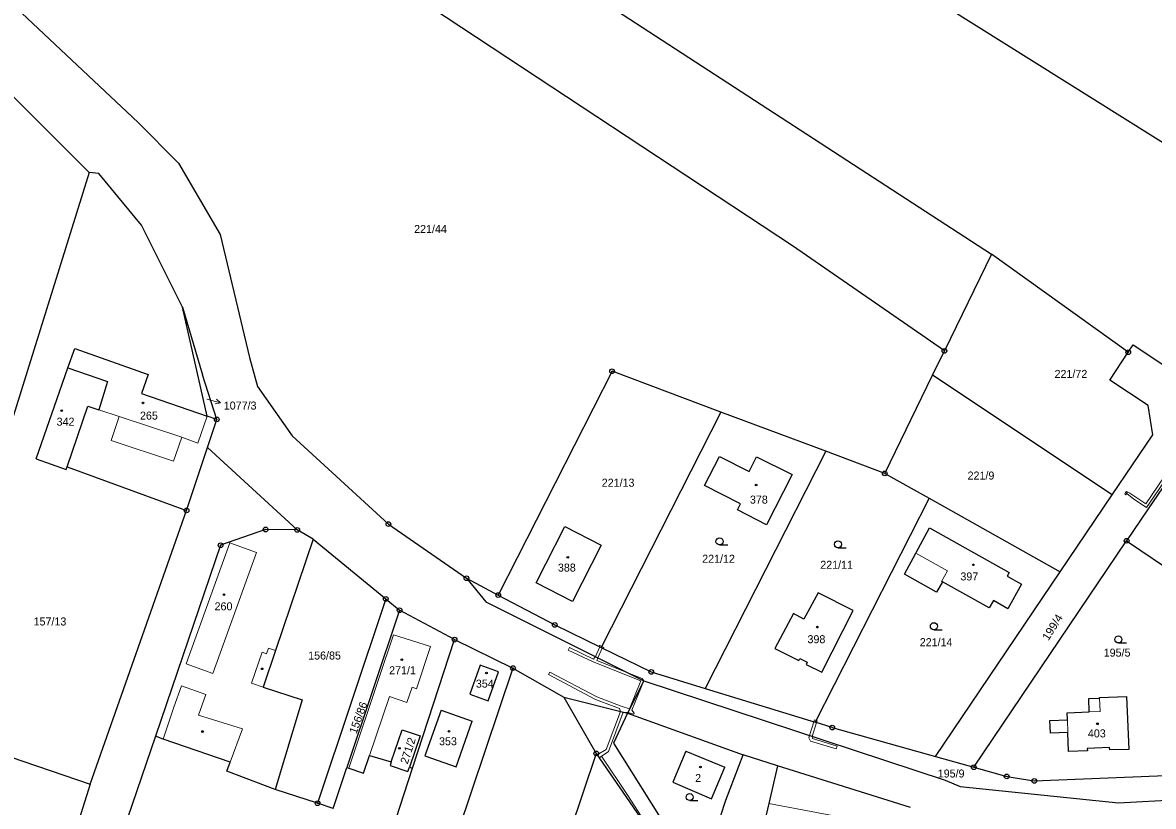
# Model space of a CAD drawing. Extents: x -694609 to -690140, y -1033292 to -1029794.
# Drawn here: x -693359.6 to -693119.3, y -1031245.2 to -1031078.6 of the extents above; entities that cross this region are included whole.
import ezdxf
from ezdxf.enums import TextEntityAlignment as Align

# ---------------------------------------------------------------- set-up
doc = ezdxf.new("R2010")
doc.units = 0
doc.header["$LTSCALE"] = 0.68
for name, color, linetype, lineweight in [('1', 7, 'Continuous', 25), ('13', 7, 'Continuous', 13), ('3', 7, 'Continuous', 25), ('4', 7, 'Continuous', 13), ('5', 7, 'Continuous', 25), ('7', 7, 'Continuous', 13), ('8', 7, 'Continuous', 25)]:
    doc.layers.add(name, color=color, linetype=linetype, lineweight=lineweight)
doc.layers.add('2', color=7, linetype='Continuous')

msp = doc.modelspace()

# ---------------------------------------------------------------- linework, layer by layer
at = {"layer": '1'}
for p, q in [((-693273.03, -1031050.26), (-693153.72, -1031127.85)), ((-693366.29, -1031070.45), (-693335.04, -1031099.87)), ((-693195.97, -1031126.12), (-693272.71, -1031075.54)), ((-693345.4, -1031110.52), (-693378.71, -1031077.22)), ((-693335.04, -1031099.87), (-693326.47, -1031108.49)), ((-693326.47, -1031108.49), (-693317.59, -1031123.7)), ((-693345.4, -1031110.52), (-693382.08, -1031227.92)), ((-693343.35, -1031110.73), (-693345.4, -1031110.52)), ((-693334.33, -1031121.69), (-693343.35, -1031110.73)), ((-693325.6, -1031139.11), (-693334.33, -1031121.69)), ((-693317.59, -1031123.7), (-693311.38, -1031149.83)), ((-693163.72, -1031148.41), (-693195.97, -1031126.12)), ((-693153.72, -1031127.85), (-693163.72, -1031148.41)), ((-693124.65, -1031148.71), (-693153.72, -1031127.85)), ((-693320.34, -1031162.28), (-693325.6, -1031139.11)), ((-693325.6, -1031139.11), (-693321.37, -1031153.47)), ((-693349.93, -1031152.01), (-693348.5, -1031147.93)), ((-693348.5, -1031147.93), (-693332.89, -1031153.42)), ((-693124.65, -1031148.71), (-693123.6, -1031147.13)), ((-693123.6, -1031147.13), (-693109.83, -1031156.28)), ((-693311.38, -1031149.83), (-693309.64, -1031155.96)), ((-693166.24, -1031153.6), (-693163.72, -1031148.41)), ((-693128.58, -1031154.62), (-693124.65, -1031148.71)), ((-693356.71, -1031171.36), (-693349.93, -1031152.01)), ((-693349.93, -1031152.01), (-693341.56, -1031154.91)), ((-693234.33, -1031152.75), (-693258.53, -1031200.3)), ((-693211.19, -1031161.42), (-693234.33, -1031152.75)), ((-693341.56, -1031154.91), (-693343.41, -1031160.93)), ((-693332.89, -1031153.42), (-693334.28, -1031157.44)), ((-693318.31, -1031162.97), (-693321.37, -1031153.47)), ((-693176.39, -1031174.45), (-693166.24, -1031153.6)), ((-693128.05, -1031178.99), (-693166.24, -1031153.6)), ((-693120.44, -1031160.04), (-693128.58, -1031154.62)), ((-693334.28, -1031157.44), (-693320.34, -1031162.28)), ((-693309.64, -1031155.96), (-693302.31, -1031166.48)), ((-693119.46, -1031166.26), (-693120.44, -1031160.04)), ((-693350.1, -1031173.03), (-693345.74, -1031160.15)), ((-693345.74, -1031160.15), (-693343.41, -1031160.93)), ((-693318.31, -1031162.97), (-693320.34, -1031162.28)), ((-693211.19, -1031161.42), (-693236.66, -1031211.46)), ((-693188.93, -1031169.75), (-693211.19, -1031161.42)), ((-693320.29, -1031168.95), (-693318.31, -1031162.97)), ((-693302.31, -1031166.48), (-693281.85, -1031185.23)), ((-693128.05, -1031178.99), (-693119.46, -1031166.26)), ((-693324.73, -1031182.33), (-693320.29, -1031168.95)), ((-693301.23, -1031186.45), (-693320.29, -1031168.95)), ((-693356.71, -1031171.36), (-693350.33, -1031173.61)), ((-693214.66, -1031177.03), (-693211.49, -1031170.86)), ((-693188.93, -1031169.75), (-693214.58, -1031220.15)), ((-693203.63, -1031170.91), (-693196.07, -1031174.71)), ((-693176.39, -1031174.45), (-693188.93, -1031169.75)), ((-693112.4, -1031170.1), (-693120.58, -1031182.22)), ((-693350.33, -1031173.61), (-693350.1, -1031173.03)), ((-693350.1, -1031173.03), (-693324.73, -1031182.33)), ((-693176.39, -1031174.45), (-693166.97, -1031179.73)), ((-693196.07, -1031174.71), (-693201.5, -1031185.39)), ((-693207.05, -1031180.94), (-693214.66, -1031177.03)), ((-693139.1, -1031195.36), (-693128.05, -1031178.99)), ((-693207.7, -1031182.21), (-693207.05, -1031180.94)), ((-693166.97, -1031179.73), (-693191.19, -1031227.33)), ((-693166.97, -1031179.73), (-693139.1, -1031195.36)), ((-693345.22, -1031240.5), (-693324.73, -1031182.33)), ((-693201.5, -1031185.39), (-693207.7, -1031182.21)), ((-693120.58, -1031182.22), (-693125, -1031188.77)), ((-693307.93, -1031186.37), (-693317.51, -1031189.73)), ((-693301.23, -1031186.45), (-693307.93, -1031186.37)), ((-693297.86, -1031188.42), (-693301.23, -1031186.45)), ((-693281.85, -1031185.23), (-693265.27, -1031196.73)), ((-693169.78, -1031191.37), (-693166.86, -1031186.01)), ((-693297.86, -1031188.42), (-693305.83, -1031212.11)), ((-693297.86, -1031188.42), (-693282.42, -1031201.11)), ((-693157.47, -1031236.89), (-693125, -1031188.77)), ((-693125, -1031188.77), (-693105.98, -1031201.7)), ((-693317.51, -1031189.73), (-693331.34, -1031230.32)), ((-693165.59, -1031234.62), (-693139.1, -1031195.36)), ((-693265.27, -1031196.73), (-693258.53, -1031200.3)), ((-693265.27, -1031196.73), (-693261.13, -1031201.72)), ((-693258.53, -1031200.3), (-693246.51, -1031206.66)), ((-693190.56, -1031199.84), (-693193.56, -1031205.43)), ((-693183.14, -1031203.56), (-693190.56, -1031199.84)), ((-693282.42, -1031201.11), (-693296.9, -1031244.56)), ((-693282.42, -1031201.11), (-693279.48, -1031203.53)), ((-693279.48, -1031203.53), (-693290.7, -1031236.94)), ((-693267.8, -1031209.78), (-693279.48, -1031203.53)), ((-693195.79, -1031204.25), (-693199.73, -1031211.69)), ((-693193.56, -1031205.43), (-693195.79, -1031204.25)), ((-693189.77, -1031216.72), (-693183.14, -1031203.56)), ((-693246.51, -1031206.66), (-693236.66, -1031211.46)), ((-693276.73, -1031237.11), (-693267.8, -1031209.78)), ((-693267.8, -1031209.78), (-693255.38, -1031215.82)), ((-693199.73, -1031211.69), (-693194.67, -1031214.24)), ((-693262.36, -1031215.21), (-693264.52, -1031221.39)), ((-693258.49, -1031216.6), (-693262.36, -1031215.21)), ((-693194.67, -1031214.24), (-693194.46, -1031213.76)), ((-693194.46, -1031213.76), (-693192.89, -1031214.58)), ((-693192.89, -1031214.58), (-693193.1, -1031215.06)), ((-693193.1, -1031215.06), (-693189.77, -1031216.72)), ((-693255.38, -1031215.82), (-693331.24, -1031440.29)), ((-693260.66, -1031222.76), (-693258.49, -1031216.6)), ((-693255.38, -1031215.82), (-693244.56, -1031222)), ((-693227.57, -1031218.56), (-693163.55, -1031239.63)), ((-693264.52, -1031221.39), (-693260.66, -1031222.76)), ((-693244.56, -1031222), (-693237.69, -1031233.95)), ((-693244.56, -1031222), (-693231.03, -1031225.43)), ((-693214.58, -1031220.15), (-693191.19, -1031227.33)), ((-693133.07, -1031222.3), (-693130.74, -1031222.24)), ((-693132.96, -1031225.13), (-693133.07, -1031222.3)), ((-693130.75, -1031222.07), (-693125.02, -1031221.85)), ((-693130.74, -1031222.24), (-693130.75, -1031222.07)), ((-693125.02, -1031221.85), (-693124.57, -1031233.09)), ((-693300.14, -1031222.56), (-693305.89, -1031241.6)), ((-693270.67, -1031224.73), (-693274.14, -1031234.44)), ((-693270.67, -1031224.73), (-693264.03, -1031227.09)), ((-693267.48, -1031236.81), (-693264.03, -1031227.09)), ((-693231.03, -1031225.43), (-693234.03, -1031231.76)), ((-693231.03, -1031225.43), (-693206.5, -1031234.28)), ((-693187.54, -1031228.45), (-693191.19, -1031227.33)), ((-693141.29, -1031226.95), (-693137.59, -1031226.83)), ((-693141.19, -1031229.62), (-693141.29, -1031226.95)), ((-693137.64, -1031225.3), (-693132.96, -1031225.13)), ((-693137.59, -1031226.83), (-693137.64, -1031225.3)), ((-693382.08, -1031227.92), (-693345.22, -1031240.5)), ((-693281.24, -1031235.78), (-693278.94, -1031228.94)), ((-693278.94, -1031228.94), (-693275.07, -1031230.25)), ((-693187.54, -1031228.45), (-693165.59, -1031234.62)), ((-693137.5, -1031229.5), (-693141.19, -1031229.62)), ((-693137.37, -1031233.54), (-693137.5, -1031229.5)), ((-693331.34, -1031230.32), (-693349.69, -1031284.17)), ((-693329.74, -1031230.95), (-693331.34, -1031230.32)), ((-693315.48, -1031235.85), (-693329.74, -1031230.95)), ((-693275.07, -1031230.25), (-693277.4, -1031236.91)), ((-693234.03, -1031231.76), (-693215.77, -1031260.84)), ((-693237.69, -1031233.95), (-693309.85, -1031446.55)), ((-693287.14, -1031238.13), (-693285.88, -1031234.42)), ((-693285.88, -1031234.42), (-693281.24, -1031235.78)), ((-693274.14, -1031234.44), (-693267.48, -1031236.81)), ((-693218.67, -1031233.45), (-693221.45, -1031240.1)), ((-693218.67, -1031233.45), (-693210.34, -1031236.89)), ((-693210.16, -1031243.87), (-693206.5, -1031234.28)), ((-693199.19, -1031236.57), (-693206.5, -1031234.28)), ((-693133.34, -1031233.4), (-693137.37, -1031233.54)), ((-693128.59, -1031233.16), (-693128.61, -1031232.73)), ((-693124.57, -1031233.09), (-693128.59, -1031233.16)), ((-693316.18, -1031237.7), (-693315.48, -1031235.85)), ((-693293.58, -1031245.65), (-693290.7, -1031236.94)), ((-693290.7, -1031236.94), (-693290.24, -1031237.12)), ((-693281.24, -1031235.78), (-693281.48, -1031236.51)), ((-693281.48, -1031236.51), (-693277.71, -1031237.8)), ((-693277.71, -1031237.8), (-693277.4, -1031236.91)), ((-693277.4, -1031236.91), (-693276.73, -1031237.11)), ((-693213.23, -1031243.61), (-693210.34, -1031236.89)), ((-693199.19, -1031236.57), (-693201.04, -1031244.57)), ((-693170.92, -1031245.42), (-693199.19, -1031236.57)), ((-693165.59, -1031234.62), (-693157.47, -1031236.89)), ((-693157.47, -1031236.89), (-693150.49, -1031238.85)), ((-693305.89, -1031241.6), (-693316.18, -1031237.7)), ((-693294.34, -1031290.95), (-693276.73, -1031237.11)), ((-693290.24, -1031237.12), (-693287.14, -1031238.13)), ((-693150.49, -1031238.85), (-693144.62, -1031239.81)), ((-693345.22, -1031240.5), (-693348.5, -1031250.94)), ((-693296.9, -1031244.56), (-693305.89, -1031241.6)), ((-693221.45, -1031240.1), (-693213.23, -1031243.61)), ((-693163.55, -1031239.63), (-693160.36, -1031241.01)), ((-693160.36, -1031241.01), (-693126.74, -1031244.44)), ((-693215.77, -1031260.84), (-693210.16, -1031243.87)), ((-693126.74, -1031244.44), (-693082.57, -1031242.07)), ((-693293.58, -1031245.65), (-693296.9, -1031244.56)), ((-693201.04, -1031244.57), (-693202.88, -1031252.55))]:
    msp.add_line(p, q, dxfattribs=at)
for points in [[(-693264.29, -1031011.93), (-693087.76, -1031122.58), (-693082.21, -1031125.35)], [(-693211.49, -1031170.86), (-693205.19, -1031174.02), (-693203.63, -1031170.91)], [(-693242.76, -1031201.64), (-693250.49, -1031197.69), (-693244.36, -1031185.74)], [(-693244.36, -1031185.74), (-693236.64, -1031189.68), (-693242.76, -1031201.64)], [(-693166.86, -1031186.01), (-693149.95, -1031195.49), (-693150.36, -1031196.27), (-693147.34, -1031197.99), (-693150.28, -1031203.2), (-693153.32, -1031201.46), (-693154.2, -1031203.03), (-693164.16, -1031197.51)], [(-693164.16, -1031197.51), (-693165.42, -1031199.7), (-693172.22, -1031195.86), (-693169.78, -1031191.37)], [(-693261.13, -1031201.72), (-693227.57, -1031218.56), (-693231.03, -1031225.43)], [(-693305.83, -1031212.11), (-693308.45, -1031219.88), (-693300.14, -1031222.56)], [(-693236.66, -1031211.46), (-693226, -1031216.64), (-693214.58, -1031220.15)], [(-693237.69, -1031233.95), (-693227.67, -1031248.57), (-693217.72, -1031264.13)], [(-693128.61, -1031232.73), (-693133.36, -1031232.92), (-693133.34, -1031233.4)], [(-693144.62, -1031239.81), (-693118.45, -1031238.73), (-693055.36, -1031236.12)]]:
    msp.add_lwpolyline(points, dxfattribs=at)
at = {"layer": '13'}
for points in [[(-693106.86, -1031161.49), (-693107.34, -1031161.14), (-693113.01, -1031169.23), (-693120.92, -1031180.9), (-693124.33, -1031178.62), (-693124.8, -1031178.47), (-693124.97, -1031178.72), (-693123.49, -1031179.9), (-693120.76, -1031181.72), (-693112.51, -1031169.57)], [(-693124.97, -1031178.72), (-693125.21, -1031178.53), (-693125.37, -1031178.78), (-693125.14, -1031178.97)], [(-693125.21, -1031178.53), (-693124.97, -1031178.72), (-693124.8, -1031178.47), (-693125.04, -1031178.28)], [(-693237.49, -1031234.24), (-693237.06, -1031234.87), (-693235.12, -1031233.53), (-693231.97, -1031225.19), (-693230.95, -1031225.27), (-693229.73, -1031225.65), (-693229.66, -1031225.41), (-693230.13, -1031224.79), (-693227.57, -1031218.56), (-693227.96, -1031218.01), (-693231.35, -1031216.66), (-693237.58, -1031214.19), (-693237.35, -1031213.65), (-693236.42, -1031211.58), (-693236.66, -1031211.46), (-693236.96, -1031211.31), (-693237.88, -1031213.39), (-693238.27, -1031213.9), (-693243.4, -1031211.45), (-693243.66, -1031211.99), (-693238.38, -1031214.52), (-693228.21, -1031218.56), (-693230.65, -1031224.48), (-693232.41, -1031223.9), (-693237.59, -1031221.95), (-693247.52, -1031216.66), (-693247.81, -1031217.19), (-693237.83, -1031222.49), (-693232.73, -1031224.42), (-693232.56, -1031225.04), (-693235.62, -1031233.15)], [(-693237.13, -1031211.23), (-693236.96, -1031211.31), (-693236.66, -1031211.46), (-693236.53, -1031211.2), (-693237, -1031210.97)], [(-693236.53, -1031211.2), (-693236.66, -1031211.46), (-693236.42, -1031211.58), (-693236.18, -1031211.69), (-693236.05, -1031211.43)], [(-693191, -1031226.96), (-693191.19, -1031227.33), (-693191.46, -1031227.25), (-693192.37, -1031230.15), (-693192.52, -1031230.64), (-693192.16, -1031231.32), (-693186.72, -1031233), (-693186.54, -1031232.42), (-693191.74, -1031230.82), (-693191.8, -1031230.33), (-693190.89, -1031227.42), (-693190.76, -1031227.03)], [(-693191.34, -1031226.85), (-693191.46, -1031227.25), (-693191.19, -1031227.33), (-693191, -1031226.96)], [(-693200.24, -1031285.53), (-693217.75, -1031262.13), (-693224.52, -1031252.92), (-693230.99, -1031242.92), (-693236.58, -1031234.54), (-693237.06, -1031234.87), (-693227.67, -1031248.57), (-693224.82, -1031253.03), (-693217.95, -1031262.64), (-693210.63, -1031273.49)]]:
    msp.add_lwpolyline(points, close=True, dxfattribs=at)
at = {"layer": '3'}
for p, q in [((-693211.503, -1031189.65), (-693209.753, -1031189.65)), ((-693186.343, -1031190.27), (-693184.593, -1031190.27)), ((-693165.953, -1031207.67), (-693164.203, -1031207.67)), ((-693126.753, -1031210.49), (-693125.003, -1031210.49)), ((-693217.833, -1031243.98), (-693216.083, -1031243.98))]:
    msp.add_line(p, q, dxfattribs=at)
for centre in [(-693211.5029, -1031188.8998), (-693186.3429, -1031189.5198), (-693165.9529, -1031206.9198), (-693126.7529, -1031209.7398), (-693217.8329, -1031243.2298)]:
    msp.add_circle(centre, 0.75, dxfattribs=at)
at = {"layer": '4'}
for p, q in [((-693343.41, -1031160.93), (-693339.05, -1031162.38)), ((-693339.05, -1031162.38), (-693340.74, -1031167.43)), ((-693339.05, -1031162.38), (-693325.77, -1031166.75)), ((-693320.34, -1031162.28), (-693322.32, -1031168.03)), ((-693325.77, -1031166.75), (-693327.48, -1031171.87)), ((-693322.32, -1031168.03), (-693325.77, -1031166.75)), ((-693327.48, -1031171.87), (-693340.74, -1031167.43)), ((-693324.82, -1031214.94), (-693315.56, -1031189.19)), ((-693315.56, -1031189.19), (-693309.89, -1031191.23)), ((-693280.77, -1031208.79), (-693283.71, -1031217.64)), ((-693280.77, -1031208.79), (-693272.9, -1031211.24)), ((-693308.7, -1031212.46), (-693310.91, -1031219.05)), ((-693307.75, -1031212.78), (-693308.7, -1031212.46)), ((-693307.35, -1031211.6), (-693307.75, -1031212.78)), ((-693305.83, -1031212.11), (-693307.35, -1031211.6)), ((-693272.9, -1031211.24), (-693275.85, -1031220.22)), ((-693290.24, -1031237.12), (-693283.71, -1031217.64)), ((-693327.44, -1031224.15), (-693325.81, -1031219.57)), ((-693325.81, -1031219.57), (-693320.61, -1031221.47)), ((-693310.91, -1031219.05), (-693308.45, -1031219.88)), ((-693276.79, -1031219.91), (-693277.93, -1031223.16)), ((-693275.85, -1031220.22), (-693276.79, -1031219.91)), ((-693322.19, -1031225.8), (-693320.61, -1031221.47)), ((-693281.63, -1031221.89), (-693285.88, -1031234.42)), ((-693277.93, -1031223.16), (-693281.63, -1031221.89)), ((-693130.74, -1031222.24), (-693130.64, -1031225.05)), ((-693329.74, -1031230.95), (-693327.44, -1031224.15)), ((-693312.83, -1031228.75), (-693322.19, -1031225.8)), ((-693137.59, -1031226.83), (-693137.5, -1031229.5)), ((-693130.64, -1031225.05), (-693132.96, -1031225.13)), ((-693315.48, -1031235.85), (-693312.83, -1031228.75)), ((-693180.43, -1031248.51), (-693201.04, -1031244.57))]:
    msp.add_line(p, q, dxfattribs=at)
for points in [[(-693324.82, -1031214.94), (-693319.15, -1031216.98), (-693309.89, -1031191.23)], [(-693169.78, -1031191.37), (-693163.07, -1031195.14), (-693164.31, -1031197.4), (-693164.16, -1031197.51)]]:
    msp.add_lwpolyline(points, dxfattribs=at)
at = {"layer": '5'}
for centre in [(-693333.9868, -1031159.4592), (-693351.2568, -1031161.0992), (-693203.7268, -1031176.9192), (-693243.7468, -1031192.2692), (-693157.5668, -1031193.8792), (-693316.7868, -1031200.2092), (-693190.7168, -1031207.1192), (-693278.9968, -1031214.0392), (-693308.6568, -1031215.9792), (-693261.0168, -1031216.8692), (-693321.3468, -1031229.3092), (-693268.9768, -1031229.2592), (-693131.2068, -1031227.6592), (-693279.5029, -1031232.8762), (-693215.5468, -1031236.8592)]:
    msp.add_circle(centre, 0.175, dxfattribs=at)
at = {"layer": '7'}
msp.add_line((-693317.561, -1031159.437), (-693318.399, -1031158.694), dxfattribs=at)
msp.add_lwpolyline([(-693320.46, -1031158.66), (-693317.561, -1031159.437), (-693318.658, -1031159.661)], dxfattribs=at)
at = {"layer": '8'}
for centre, radius in [((-693163.72, -1031148.4099), 0.5), ((-693163.72, -1031148.4099), 0.0303), ((-693124.65, -1031148.7099), 0.5), ((-693124.65, -1031148.7099), 0.0303), ((-693234.33, -1031152.7499), 0.5), ((-693234.33, -1031152.7499), 0.0303), ((-693318.31, -1031162.9699), 0.5), ((-693318.31, -1031162.9699), 0.0303), ((-693176.39, -1031174.4499), 0.5), ((-693176.39, -1031174.4499), 0.0303), ((-693324.73, -1031182.3299), 0.5), ((-693324.73, -1031182.3299), 0.0303), ((-693307.93, -1031186.3699), 0.5), ((-693307.93, -1031186.3699), 0.0303), ((-693301.23, -1031186.4499), 0.5), ((-693301.23, -1031186.4499), 0.0303), ((-693281.85, -1031185.2299), 0.5), ((-693281.85, -1031185.2299), 0.0303), ((-693125, -1031188.7699), 0.5), ((-693125, -1031188.7699), 0.0303), ((-693317.51, -1031189.7299), 0.5), ((-693317.51, -1031189.7299), 0.0303), ((-693265.27, -1031196.7299), 0.5), ((-693265.27, -1031196.7299), 0.0303), ((-693282.42, -1031201.1099), 0.5), ((-693258.53, -1031200.2999), 0.5), ((-693258.53, -1031200.2999), 0.0303), ((-693282.42, -1031201.1099), 0.0303), ((-693279.48, -1031203.5299), 0.5), ((-693279.48, -1031203.5299), 0.0303), ((-693246.51, -1031206.6599), 0.5), ((-693246.51, -1031206.6599), 0.0303), ((-693267.8, -1031209.7799), 0.5), ((-693267.8, -1031209.7799), 0.0303), ((-693255.38, -1031215.8199), 0.5), ((-693255.38, -1031215.8199), 0.0303), ((-693226, -1031216.6399), 0.5), ((-693226, -1031216.6399), 0.0303), ((-693187.54, -1031228.4499), 0.5), ((-693187.54, -1031228.4499), 0.0303), ((-693237.69, -1031233.9499), 0.5), ((-693237.69, -1031233.9499), 0.0303), ((-693157.47, -1031236.8899), 0.5), ((-693157.47, -1031236.8899), 0.0303), ((-693150.49, -1031238.8499), 0.5), ((-693150.49, -1031238.8499), 0.0303), ((-693144.62, -1031239.8099), 0.5), ((-693144.62, -1031239.8099), 0.0303), ((-693296.9, -1031244.5599), 0.5), ((-693296.9, -1031244.5599), 0.0303)]:
    msp.add_circle(centre, radius, dxfattribs=at)

# ---------------------------------------------------------------- texts
at = {"layer": '2'}
for s, p in [('221/44', (-693272.91, -1031123.355)), ('221/72', (-693136.84, -1031154.155)), ('265', (-693332.739, -1031163.015)), ('342', (-693350.449, -1031164.315)), ('221/9', (-693155.95, -1031175.755)), ('221/13', (-693233.05, -1031177.275)), ('388', (-693243.939, -1031195.312)), ('221/12', (-693211.71, -1031193.435)), ('221/11', (-693186.62, -1031194.725)), ('397', (-693158.429, -1031197.195)), ('260', (-693316.889, -1031203.545)), ('157/13', (-693353.76, -1031206.765)), ('156/85', (-693295.42, -1031214.005)), ('195/5', (-693127.03, -1031213.385)), ('271/1', (-693278.85, -1031217.135)), ('403', (-693131.339, -1031230.552)), ('353', (-693269.199, -1031232.225)), ('2', (-693216.05, -1031240.035)), ('195/9', (-693162.29, -1031239.075))]:
    msp.add_text(s, height=1.7, dxfattribs=at).set_placement(p, align=Align.CENTER)
for s, p in [('1077/3', (-693316.83, -1031160.882)), ('378', (-693205.04, -1031180.865)), ('398', (-693192.81, -1031210.535)), ('221/14', (-693168.96, -1031211.165)), ('354', (-693263.27, -1031219.975))]:
    msp.add_text(s, height=1.7, dxfattribs=at).set_placement(p)
at = {"layer": '2', "width": 1.05}
msp.add_text('199/4', height=1.7, rotation=58, dxfattribs=at).set_placement((-693140.0461, -1031207.5959), align=Align.CENTER)
at = {"layer": '2'}
for s, rotation, p in [('156/86', 70, (-693287.4566, -1031226.6567)), ('271/2', 72, (-693276.882, -1031233.6267))]:
    msp.add_text(s, height=1.7, rotation=rotation, dxfattribs=at).set_placement(p, align=Align.CENTER)

doc.saveas('drawing.dxf')
